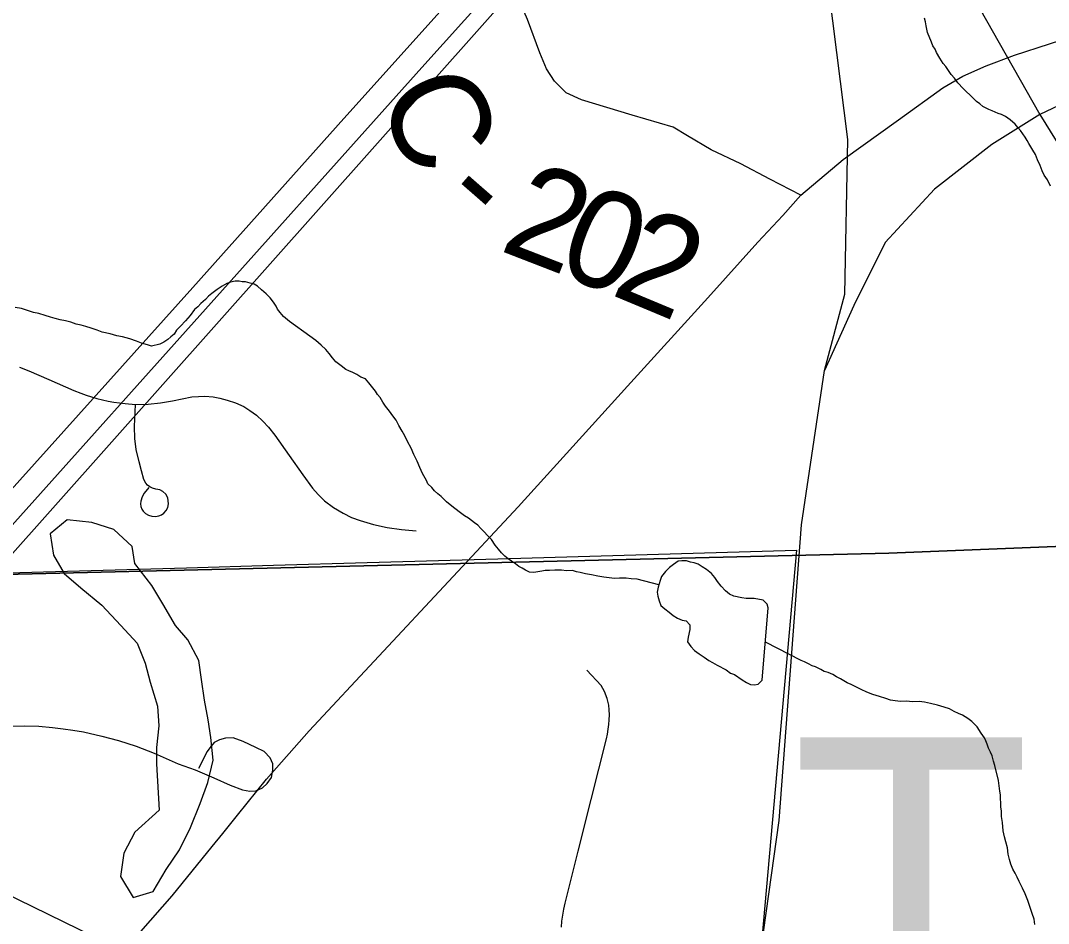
# Model space of a CAD drawing. Extents: x -6.1 to 38, y -7.7 to 22.
# Drawn here: x 5.6 to 6.198, y 19.227 to 19.753 of the extents above; entities that cross this region are included whole.
import ezdxf

# ---------------------------------------------------------------- set-up
doc = ezdxf.new("R2010")
doc.units = 0
for name, color, linetype in [('GM_X_City_Street', 7, 'Continuous'), ('GM_X_Corporation', 7, 'Continuous'), ('GM_X_County_Road', 7, 'Continuous'), ('GM_X_County_Road_Text', 7, 'Continuous'), ('GM_X_Minor_Lake', 7, 'Continuous'), ('GM_X_Minor_River', 7, 'Continuous'), ('GM_X_Rail_Line', 7, 'Continuous'), ('GM_X_Township_Road', 7, 'Continuous'), ('GM_X_Township_Text', 7, 'Continuous'), ('GM_X_US_Route', 7, 'Continuous'), ('SH_Text', 7, 'Continuous')]:
    doc.layers.add(name, color=color, linetype=linetype)

msp = doc.modelspace()

# ---------------------------------------------------------------- linework, layer by layer
at = {"layer": 'GM_X_City_Street'}
for points in [[(5.59905, 19.55104), (5.60448, 19.54894), (5.61607, 19.54389), (5.63064, 19.53759), (5.63458, 19.53596), (5.6377, 19.53481), (5.64088, 19.53375), (5.64405, 19.53283), (5.64732, 19.53201), (5.65059, 19.5313), (5.65386, 19.5307), (5.65718, 19.53023), (5.6605, 19.52986), (5.66639, 19.52931), (5.67385, 19.52958), (5.68106, 19.53037), (5.68802, 19.53153), (5.69934, 19.53375), (5.70315, 19.53407), (5.70685, 19.53418), (5.71164, 19.53375), (5.71555, 19.53298), (5.71991, 19.53189), (5.72468, 19.53035), (5.72949, 19.52819), (5.73298, 19.5259), (5.73693, 19.52311), (5.74063, 19.51974), (5.74383, 19.5162), (5.74754, 19.51152), (5.756, 19.49976), (5.76387, 19.48837), (5.76948, 19.48069), (5.77285, 19.477), (5.77647, 19.47338), (5.78165, 19.46951), (5.78727, 19.46613), (5.79217, 19.46368), (5.79718, 19.46178), (5.805, 19.45951), (5.81289, 19.45787), (5.82131, 19.45655), (5.82988, 19.45579)], [(5.67418, 19.48115), (5.67148, 19.47778), (5.67027, 19.4757), (5.66955, 19.47306), (5.6694, 19.47147), (5.66952, 19.46994), (5.67008, 19.46853), (5.67099, 19.46719), (5.67234, 19.46597), (5.67412, 19.4649), (5.67607, 19.46438), (5.67822, 19.46425), (5.68006, 19.4646), (5.68158, 19.46523), (5.68305, 19.46603), (5.6844, 19.46768), (5.68531, 19.46945), (5.68561, 19.47153), (5.68533, 19.47502), (5.68415, 19.47716), (5.68243, 19.4788), (5.68066, 19.47961), (5.67833, 19.48016), (5.67638, 19.48066), (5.67479, 19.48139), (5.6735, 19.48249), (5.67247, 19.48353), (5.67142, 19.48579), (5.66995, 19.49075), (5.66857, 19.49602), (5.66693, 19.50309), (5.66617, 19.50962), (5.66596, 19.51658), (5.66639, 19.52931)]]:
    msp.add_lwpolyline(points, dxfattribs=at)
at = {"layer": 'GM_X_Corporation'}
for points in [[(4.22089, 19.39843), (4.27649, 19.3997), (4.32704, 19.40086), (4.34441, 19.40116), (4.39909, 19.40211), (4.59553, 19.40667), (4.87412, 19.41274), (4.97606, 19.41491), (5.07728, 19.4172), (5.13005, 19.41862), (5.18283, 19.42005), (5.26822, 19.42235), (5.32463, 19.42402), (6.10501, 19.44291), (6.34755, 19.45258), (6.9731, 19.47266), (6.99327, 19.47331), (6.9774, 20.19314), (6.97663, 20.24175), (6.97563, 20.30513), (6.97445, 20.38052), (6.96628, 20.9), (2.1, 20.9)], [(7.03821, 16.8882), (6.99349, 19.46054), (6.99327, 19.47331), (6.9731, 19.47266), (6.34755, 19.45258), (6.10501, 19.44291), (5.32463, 19.42402), (5.26822, 19.42235), (5.18283, 19.42005), (5.13005, 19.41862), (5.07728, 19.4172), (4.97606, 19.41491), (4.87412, 19.41274), (4.59553, 19.40667), (4.39909, 19.40211), (4.34441, 19.40116), (4.32704, 19.40086), (4.27649, 19.3997), (4.22089, 19.39843)], [(5.35638, 19.42473), (5.69625, 19.43438), (5.74676, 19.43582), (5.80141, 19.4374), (5.87749, 19.43958), (6.05133, 19.44458), (6.02484, 19.14859)]]:
    msp.add_lwpolyline(points, dxfattribs=at)
at = {"layer": 'GM_X_County_Road'}
for points in [[(6.05383, 19.65114), (6.03582, 19.66052), (6.01879, 19.66941), (6.00152, 19.67755), (5.98778, 19.68565), (5.97939, 19.69069), (5.95562, 19.69778), (5.92601, 19.70666), (5.91708, 19.71078), (5.91046, 19.71752), (5.90566, 19.72458), (5.90179, 19.7339), (5.89458, 19.75342), (5.88289, 19.78076)], [(5.66962, 19.22276), (5.68788, 19.24349), (5.71107, 19.27211), (5.71724, 19.27976), (5.72588, 19.29037), (5.74266, 19.31135), (5.76758, 19.33948), (5.88924, 19.46977), (5.95291, 19.5401), (5.99955, 19.59142), (6.02866, 19.62375), (6.04322, 19.6393), (6.05383, 19.65114), (6.07851, 19.67187), (6.11059, 19.69507), (6.1365, 19.71357), (6.1481, 19.72048), (6.16167, 19.7264), (6.1782, 19.73257), (6.21892, 19.7459)]]:
    msp.add_lwpolyline(points, dxfattribs=at)
at = {"layer": 'GM_X_Minor_Lake'}
msp.add_line((6.03133, 19.36887), (6.03479, 19.41095), dxfattribs=at)
for points in [[(5.68972, 19.40083), (5.68247, 19.41334), (5.67599, 19.42396), (5.6661, 19.43684), (5.66454, 19.4467), (5.6539, 19.45655), (5.64101, 19.46069), (5.62663, 19.46217), (5.61682, 19.45418), (5.61877, 19.44166), (5.62487, 19.43104), (5.63474, 19.42272), (5.6469, 19.4125), (5.65792, 19.40076), (5.66743, 19.39053), (5.67202, 19.37877), (5.6751, 19.36777), (5.67932, 19.35374), (5.68013, 19.34235), (5.67867, 19.32982), (5.67871, 19.32034), (5.68024, 19.29328)], [(6.03479, 19.41095), (6.03408, 19.41324), (6.03185, 19.41556), (6.02657, 19.41642), (6.02203, 19.4165), (6.01939, 19.41693), (6.01486, 19.41777), (6.01223, 19.41896), (6.01, 19.4209), (6.0074, 19.42361), (6.00518, 19.42631), (6.00371, 19.42861), (6.00186, 19.43093), (5.99888, 19.43326), (5.99626, 19.43483), (5.99402, 19.43639), (5.99176, 19.43719), (5.9895, 19.43761), (5.98724, 19.43841), (5.98459, 19.43846), (5.98232, 19.43812), (5.97963, 19.43627), (5.97732, 19.43442), (5.97501, 19.43219), (5.97268, 19.42919), (5.97188, 19.42693), (5.97067, 19.42315), (5.97024, 19.42012), (5.97057, 19.41784), (5.97128, 19.41517), (5.97236, 19.41249), (5.97459, 19.41055), (5.97721, 19.4086), (5.97944, 19.40666), (5.98206, 19.40509), (5.98468, 19.4039), (5.98695, 19.40348), (5.98918, 19.40116), (5.98913, 19.39851), (5.98828, 19.39397), (5.98785, 19.39132), (5.98969, 19.38862), (5.99192, 19.3863), (5.99453, 19.38436), (5.99752, 19.3824), (6.00014, 19.38046), (6.00238, 19.37927), (6.005, 19.37771), (6.01025, 19.37495), (6.01286, 19.373), (6.01512, 19.3722), (6.0196, 19.36908), (6.02222, 19.36751), (6.02447, 19.36633), (6.02674, 19.36629), (6.02902, 19.36663), (6.03133, 19.36887)], [(5.68024, 19.29328), (5.66601, 19.28045), (5.65963, 19.26828), (5.65779, 19.25462), (5.66504, 19.24249), (5.67676, 19.24593), (5.68427, 19.25885), (5.69217, 19.27026), (5.69855, 19.28318), (5.70416, 19.29724), (5.70865, 19.3094), (5.71163, 19.32231), (5.71043, 19.3356), (5.70887, 19.34584), (5.70656, 19.35722), (5.70499, 19.36936), (5.70343, 19.38037), (5.69694, 19.3925), (5.68972, 19.40083)]]:
    msp.add_lwpolyline(points, dxfattribs=at)
at = {"layer": 'GM_X_Minor_River'}
for points in [[(5.21821, 19.01967), (5.96039, 19.85374), (6.00977, 19.91076), (6.01579, 19.92025), (6.02672, 19.93242), (6.03954, 19.94611), (6.05199, 19.95714), (6.06595, 19.96818), (6.07916, 19.97732), (6.09199, 19.98949), (6.10293, 19.99863), (6.11614, 20.00966), (6.12595, 20.01538), (6.13652, 20.02262), (6.14897, 20.03289), (6.16294, 20.04317), (6.17351, 20.04889), (6.18786, 20.0569), (6.19768, 20.06148), (6.21279, 20.06759)], [(6.19901, 19.65631), (6.19742, 19.66009), (6.19547, 19.66271), (6.19429, 19.66536), (6.1931, 19.66837), (6.19151, 19.67177), (6.19032, 19.67479), (6.18875, 19.67742), (6.18758, 19.6793), (6.18641, 19.68118), (6.18561, 19.68307), (6.18444, 19.68495), (6.18172, 19.68871), (6.18016, 19.69058), (6.17861, 19.69245), (6.17553, 19.69506), (6.17283, 19.69691), (6.17054, 19.69801), (6.16862, 19.69874), (6.16518, 19.7002), (6.16327, 19.70092), (6.15981, 19.70276), (6.15789, 19.70425), (6.15596, 19.70574), (6.15403, 19.7076), (6.1521, 19.70947), (6.15017, 19.71134), (6.14823, 19.7132), (6.14514, 19.71657), (6.14319, 19.7192), (6.14125, 19.72144), (6.13969, 19.7237), (6.13813, 19.72595), (6.13658, 19.72782), (6.13462, 19.73083), (6.13266, 19.73422), (6.13187, 19.73611), (6.1307, 19.73799), (6.1299, 19.74025), (6.12752, 19.74591), (6.1271, 19.74781), (6.12669, 19.7497), (6.12627, 19.75198), (6.12585, 19.75425)], [(5.71957, 19.59981), (5.71694, 19.59824), (5.71394, 19.59628), (5.71094, 19.59395), (5.70907, 19.59239), (5.70721, 19.59046), (5.70459, 19.58813), (5.70272, 19.5862), (5.70086, 19.58464), (5.69826, 19.58117), (5.69565, 19.57808), (5.69267, 19.57499), (5.69043, 19.57267), (5.68896, 19.57036), (5.68709, 19.5688), (5.68522, 19.56725), (5.68296, 19.56569), (5.68071, 19.56451), (5.67579, 19.56328), (5.6735, 19.564), (5.67006, 19.56508), (5.667, 19.56616), (5.66318, 19.56761), (5.65898, 19.56868), (5.65555, 19.56938), (5.65173, 19.57045), (5.64716, 19.57151), (5.6441, 19.5726), (5.64066, 19.57368), (5.6376, 19.57476), (5.63493, 19.57547), (5.63188, 19.57618), (5.62882, 19.57726), (5.62577, 19.57797), (5.62272, 19.57868), (5.61967, 19.57938), (5.617, 19.5801), (5.61394, 19.58118), (5.61012, 19.58225), (5.60707, 19.58296), (5.60363, 19.58404), (5.6002, 19.58512), (5.59639, 19.58581)], [(5.97105, 19.42433), (5.95852, 19.42765), (5.95509, 19.42796), (5.95205, 19.42829), (5.94825, 19.42822), (5.94522, 19.42817), (5.94217, 19.42849), (5.93913, 19.42882), (5.9357, 19.42952), (5.93189, 19.43021), (5.92846, 19.43091), (5.9254, 19.43162), (5.92312, 19.43196), (5.92083, 19.43268), (5.91741, 19.43261), (5.91437, 19.43294), (5.91057, 19.43287), (5.90753, 19.43282), (5.90487, 19.43277), (5.90298, 19.43236), (5.90071, 19.43193), (5.89844, 19.43151), (5.89578, 19.43184), (5.89348, 19.43294), (5.89156, 19.43405), (5.88964, 19.43516), (5.88771, 19.43664), (5.88541, 19.43812), (5.88348, 19.43961), (5.88156, 19.4411), (5.87962, 19.44296), (5.87769, 19.44521), (5.87575, 19.44746), (5.87379, 19.45084), (5.87147, 19.45308), (5.86953, 19.45533), (5.86759, 19.4572), (5.86566, 19.45907), (5.86374, 19.46055), (5.86027, 19.46315), (5.85797, 19.46463), (5.85489, 19.46686), (5.85065, 19.4702), (5.84757, 19.47281), (5.84447, 19.4758), (5.84255, 19.47728), (5.84061, 19.47915), (5.83906, 19.48102), (5.83674, 19.48326), (5.83595, 19.48515), (5.8336, 19.48929), (5.83202, 19.49269), (5.83043, 19.49646), (5.82846, 19.50023), (5.82688, 19.504), (5.82491, 19.50777), (5.82333, 19.51116), (5.82176, 19.5138), (5.8198, 19.51719), (5.81823, 19.5202), (5.81628, 19.52283), (5.81434, 19.52545), (5.812, 19.52845), (5.81044, 19.53071), (5.80888, 19.53334), (5.80732, 19.53522), (5.80615, 19.5371), (5.80382, 19.5401), (5.80227, 19.54197), (5.80033, 19.54422), (5.79765, 19.54531), (5.79534, 19.54679), (5.79305, 19.54789), (5.79075, 19.54899), (5.78884, 19.54971), (5.78614, 19.55195), (5.78306, 19.55417), (5.78112, 19.55642), (5.77917, 19.55905), (5.77723, 19.56129), (5.77453, 19.56391), (5.77144, 19.56651), (5.76798, 19.56911), (5.75605, 19.57765), (5.75258, 19.58062), (5.75064, 19.58287), (5.74909, 19.58475), (5.74829, 19.58663), (5.74673, 19.58889), (5.74479, 19.59151), (5.74247, 19.59375), (5.73977, 19.59599), (5.73745, 19.59823), (5.73553, 19.59933), (5.73324, 19.60005), (5.73057, 19.60077), (5.72867, 19.60073), (5.72676, 19.60108), (5.72449, 19.60104), (5.72184, 19.60061), (5.71957, 19.59981)], [(6.16427, 19.32714), (6.16309, 19.3294), (6.16229, 19.33167), (6.1615, 19.33355), (6.16071, 19.33544), (6.15876, 19.33807), (6.15641, 19.34183), (6.15332, 19.34482), (6.15101, 19.34668), (6.14794, 19.34852), (6.14564, 19.34962), (6.14296, 19.35071), (6.14028, 19.35219), (6.13722, 19.35327), (6.1334, 19.35435), (6.12921, 19.35541), (6.12577, 19.35611), (6.12273, 19.35644), (6.11893, 19.35637), (6.11513, 19.35668), (6.11171, 19.35662), (6.10867, 19.35694), (6.106, 19.35728), (6.10333, 19.35837), (6.09951, 19.35944), (6.09569, 19.36052), (6.09225, 19.36197), (6.0888, 19.36344), (6.08612, 19.36491), (6.08305, 19.36637), (6.08075, 19.36747), (6.07692, 19.36969), (6.07462, 19.37079), (6.07231, 19.37226), (6.06963, 19.37336), (6.06734, 19.37408), (6.06542, 19.37518), (6.06236, 19.37665), (6.06045, 19.37738), (6.05815, 19.37847), (6.05585, 19.37958), (6.05394, 19.3803), (6.03316, 19.3911)], [(6.19, 19.22683), (6.18957, 19.22986), (6.18837, 19.23326), (6.18717, 19.23666), (6.18595, 19.24083), (6.18437, 19.2446), (6.18279, 19.24799), (6.18082, 19.25176), (6.17963, 19.2544), (6.17845, 19.25666), (6.17727, 19.25892), (6.17608, 19.26194), (6.17527, 19.26459), (6.17446, 19.26762), (6.17401, 19.27141), (6.17319, 19.27482), (6.17238, 19.27785), (6.17156, 19.28126), (6.17109, 19.28619), (6.17065, 19.28961), (6.17059, 19.29265), (6.17016, 19.2953), (6.17012, 19.29758), (6.17008, 19.29987), (6.17004, 19.30215), (6.16962, 19.30442), (6.16919, 19.30745), (6.16875, 19.31049), (6.1667, 19.3192), (6.16589, 19.32184), (6.16507, 19.32487), (6.16427, 19.32714)]]:
    msp.add_lwpolyline(points, dxfattribs=at)
at = {"layer": 'GM_X_Rail_Line'}
for points in [[(6.3285, 20.18713), (6.34181, 19.74734), (6.32368, 19.73124), (6.28711, 19.72545), (6.23311, 19.71713), (6.19287, 19.69813)], [(5.98253, 20.0867), (6.03146, 19.98114), (6.07204, 19.91118), (6.19287, 19.69813)], [(6.06761, 19.54911), (6.07941, 19.59351), (6.08118, 19.68356), (6.06593, 19.80342), (6.04311, 19.86981), (6.01482, 19.92343), (5.99775, 19.98381), (5.986, 20.03637), (5.98253, 20.0867)], [(6.19287, 19.69813), (6.16486, 19.68067), (6.13164, 19.65458), (6.10292, 19.62355), (6.08464, 19.58687), (6.06761, 19.54911)], [(6.19287, 19.69813), (6.21792, 19.65768), (6.25419, 19.613), (6.2935, 19.58374), (6.34004, 19.56589), (6.38312, 19.55199), (6.4273, 19.55367), (6.48418, 19.56365), (6.64401, 19.60019), (6.71957, 19.61741), (6.76764, 19.62675), (6.84656, 19.6383), (7.43863, 19.63931), (7.50222, 19.63795), (7.56146, 19.62521), (7.63701, 19.60108), (7.88712, 19.52077), (7.95726, 19.49994), (8.00695, 19.47618), (8.05679, 19.43987), (8.28809, 19.27109), (8.78458, 18.9138), (8.9, 18.83346)], [(6.01392, 19.09362), (6.04108, 19.2873), (6.05407, 19.45932), (6.06761, 19.54911)]]:
    msp.add_lwpolyline(points, dxfattribs=at)
at = {"layer": 'GM_X_Township_Road'}
for points in [[(5.9144, 19.22527), (5.91473, 19.22867), (5.91521, 19.23221), (5.91587, 19.23573), (5.91668, 19.23921), (5.92422, 19.26935), (5.93177, 19.29948), (5.93619, 19.31715), (5.94061, 19.33481), (5.94122, 19.33756), (5.9417, 19.34034), (5.94203, 19.34314), (5.94222, 19.34596), (5.94232, 19.34878), (5.94222, 19.3516), (5.94199, 19.35442), (5.94108, 19.35833), (5.93946, 19.36226), (5.9375, 19.36593), (5.92929, 19.37473)], [(5.59103, 19.34225), (5.60198, 19.34238), (5.61013, 19.34218), (5.61822, 19.34133), (5.62441, 19.34069), (5.63008, 19.3399), (5.63621, 19.33892), (5.64684, 19.33638), (5.65662, 19.3339), (5.66685, 19.33051), (5.67728, 19.32641), (5.69123, 19.32035), (5.70128, 19.31669), (5.71208, 19.31203), (5.72154, 19.30782), (5.72883, 19.30509), (5.73305, 19.30429), (5.73658, 19.30463), (5.74045, 19.30634), (5.74319, 19.30885), (5.74558, 19.31238), (5.74649, 19.31659), (5.74637, 19.32035), (5.74478, 19.32377), (5.74136, 19.32753), (5.73658, 19.32981), (5.72918, 19.33334), (5.72336, 19.33539), (5.7188, 19.33528), (5.71539, 19.33414), (5.71231, 19.33266), (5.70969, 19.32958), (5.70821, 19.32742), (5.7032, 19.31762)]]:
    msp.add_lwpolyline(points, dxfattribs=at)
at = {"layer": 'GM_X_US_Route'}
for points in [[(5.03183, 18.88699), (5.03441, 18.89324), (5.0406, 18.89993), (5.0609, 18.9132), (5.08696, 18.93231), (5.11714, 18.95663), (5.13994, 18.97748), (5.18251, 19.02026), (5.21725, 19.05934), (5.24548, 19.09062), (5.38511, 19.2461), (5.46459, 19.33557), (5.54102, 19.42069), (5.69977, 19.59745), (5.78771, 19.69583), (5.87696, 19.79507)], [(5.22096, 19.04223), (5.245, 19.06931), (5.39336, 19.23481), (5.54633, 19.40534), (5.68905, 19.56449), (5.83324, 19.72538), (5.88289, 19.78076)]]:
    msp.add_lwpolyline(points, dxfattribs=at)
at = {"layer": 'SH_Text'}
msp.add_lwpolyline([(5.44879, 19.3143), (6.62446, 18.73967), (5.44915, 18.64981)], close=True, dxfattribs=at)

# ---------------------------------------------------------------- texts
at = {"layer": 'GM_X_County_Road_Text'}
for s, rotation, p in [('C', 295.12843, (5.80618, 19.70847)), ('2', 338.82599, (5.87734, 19.61938)), ('-', 318.91254, (5.84139, 19.6458)), ('0', 337.92415, (5.90976, 19.60682)), ('2', 337.34531, (5.94206, 19.59372))]:
    msp.add_text(s, height=0.05682, rotation=rotation, dxfattribs=at).set_placement(p)
at = {"layer": 'GM_X_Township_Text'}
msp.add_text('TUSCARAWAS', height=0.170455, rotation=0.00001, dxfattribs=at).set_placement((6.04843, 19.16529))

doc.saveas('drawing.dxf')
